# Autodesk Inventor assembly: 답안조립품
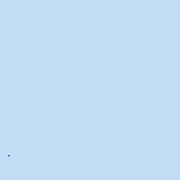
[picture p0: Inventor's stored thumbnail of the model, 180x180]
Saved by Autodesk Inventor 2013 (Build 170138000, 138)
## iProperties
Created: 2016-01
Part Number: 답안조립품
Document SubType Name: Assembly
Designer: Administrator
Author: Administrator
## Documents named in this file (16)
- C:\Users\Administrator\Desktop\460106V1040\답안조립품.iam
- C:\Users\Administrator\Desktop\460106V1040\V-벨트풀리.ipt
- C:\Users\Administrator\Desktop\460106V1040\뒤커버.ipt
- C:\Users\Administrator\Desktop\460106V1040\멈춤나사 - M4x10.ipt
- C:\Users\Administrator\Desktop\460106V1040\베어링 6203.ipt
- C:\Users\Administrator\Desktop\460106V1040\본체.ipt
- C:\Users\Administrator\Desktop\460106V1040\볼트 M3 x 8.ipt
- C:\Users\Administrator\Desktop\460106V1040\볼트 M3 x 10.ipt
- C:\Users\Administrator\Desktop\460106V1040\부시1.ipt
- C:\Users\Administrator\Desktop\460106V1040\부시2.ipt
- C:\Users\Administrator\Desktop\460106V1040\스퍼기어.ipt
- C:\Users\Administrator\Desktop\460106V1040\앞커버.ipt
- C:\Users\Administrator\Desktop\460106V1040\오일씰 28 40 8.ipt
- C:\Users\Administrator\Desktop\460106V1040\축.ipt
- C:\Users\Administrator\Desktop\460106V1040\키 - 5 x 5 x 18.ipt
- C:\Users\Administrator\Desktop\460106V1040\키 - 6 x 6 x 22.ipt
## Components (3 placed, 3 different names)
1. V-벨트풀리:1
2. ISO 4762 M3 x 8:1
3. ISO 4762 M3 x 10:1
